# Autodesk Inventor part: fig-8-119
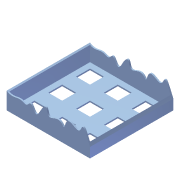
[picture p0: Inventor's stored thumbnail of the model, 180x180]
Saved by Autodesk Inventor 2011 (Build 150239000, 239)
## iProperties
Shininess: 64.0
Length Units: 11269
Angle Units: 11279
Time Units: 11290
Mass Units: 11283
Length Display Precision: 3
Angle Display Precision: 2
Compacted: True
Part Number: fig-8-119
Document SubType Name: Modeling
Created: 2002-12
Designer: deepak
Density: 1 g/cm^3
Density: 0.0
Volumn: 0.0
Area: 0.0
PropertySet Name: Model Information
Control State: 0
Master: False
Checked Out: False
Author: deepak
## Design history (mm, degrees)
sketch "Sketch1"
  geometry: L1 (-32.188, 30.089)-(27.812, 30.089); L2 (27.812, 30.089)-(27.812, -29.911); L3 (27.812, -29.911)-(-32.188, -29.911); L4 (-32.188, -29.911)-(-32.188, 30.089)
  constraints: 8 end point, 2 parallel, 1 horizontal, 1 perpendicular
  dimensions: "d0" = 60 distance of L1.start L1.end; "d1" = 60 distance of L3.end L1.start
extrude "Extrusion1" new body sketch "Sketch1" stored distance "d2" = 20; taper "d3" = 0 deg
shell "Shell2" dims "d21" = 1
sketch "Sketch5"
  geometry: L1 (-27.812, 30.089)-(32.188, 30.089) reference; L2 (-27.812, -29.911)-(-27.812, 30.089) reference; L3 (-22.812, 25.089)-(-12.812, 25.089); L4 (-12.812, 25.089)-(-12.812, 15.089); L5 (-12.812, 15.089)-(-22.812, 15.089); L6 (-22.812, 15.089)-(-22.812, 25.089)
  constraints: 8 end point, 2 parallel, 1 horizontal, 1 perpendicular
  dimensions: "d8" = 10 distance of L3.start L3.end; "d9" = 10 distance of L5.end L3.start; "d10" = 5 distance between parallel lines of L2 L6; "d11" = 5 distance between parallel lines of L1 L3
extrude "Extrusion2" cut sketch "Sketch5" distance "d12" = 50; taper "d13" = 0 deg
pattern_linear "Rectangular Pattern1" dims "d16" = 20
sketch "Sketch2"
  geometry: 17 further points
  constraints: 17 other
extrude_surface "ExtrusionSrf1" sketch "Sketch2" dims "d4" = 70, "d5" = 0
split "Split2"
body "Solid1"
body "Srf1"
